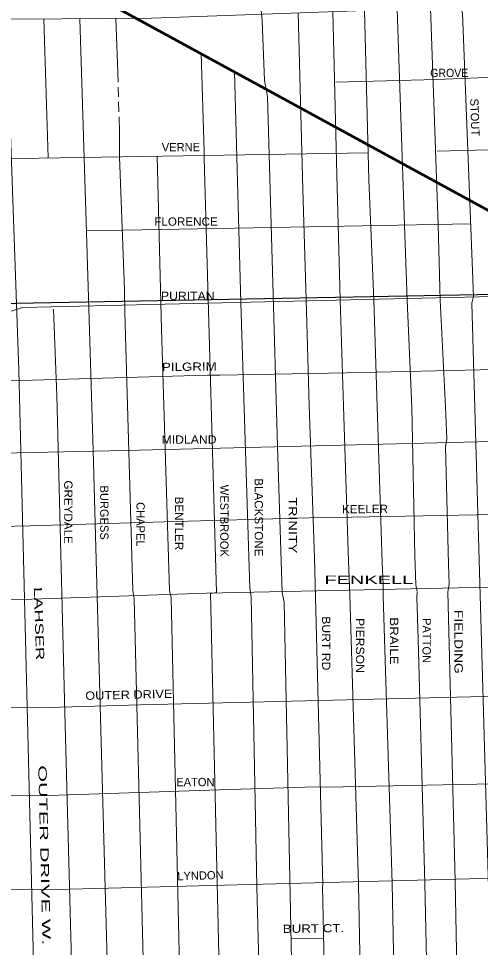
# Model space of a CAD drawing. Extents: x 34705 to 138605, y 34275 to 143551.
# Drawn here: x 43181 to 47356, y 121964 to 130370 of the extents above; entities that cross this region are included whole.
import ezdxf
from ezdxf.enums import TextEntityAlignment as Align

# ---------------------------------------------------------------- set-up
doc = ezdxf.new("R2010")
doc.units = 0
doc.header["$LTSCALE"] = 30
doc.linetypes.add('MEDIUM_DASHED', pattern=[4.5, 3, -1.5])
doc.layers.add('1', color=7, linetype='Continuous', lineweight=13)
doc.layers.add('11', color=7, linetype='Continuous', lineweight=13)

msp = doc.modelspace()

# ---------------------------------------------------------------- linework, layer by layer
at = {"layer": '1'}
for p, q in [((43409.69, 130365.58), (43448.1, 129108.82)), ((44058.94, 130369.94), (44077.55, 129885.39)), ((44092.23, 129381.05), (44093.84, 129119.21)), ((46965.59, 129170.84), (49690.15, 129237.44)), ((42382.42, 129091.68), (46341.01, 129155.36)), ((45644.76, 122041.69), (45938.46, 122045.94))]:
    msp.add_line(p, q, dxfattribs=at)
at = {"layer": '1', "linetype": 'MEDIUM_DASHED'}
msp.add_line((44077.55, 129885.39), (44090.41, 129443.69), dxfattribs=at)
at = {"layer": '1'}
for points in [[(45022.9, 140919.65), (45146.05, 135811.43), (45168.09, 135651.55), (45234.23, 133875), (45372.01, 130476.24), (45383.03, 130349.45), (45405.07, 129809.17), (45432.63, 129665.83), (45520.81, 126500.01), (45564.9, 125176.89), (45581.43, 125088.68), (45688.51, 119936.3)], [(42731.15, 140854.29), (42770.72, 138315.69), (42820.32, 138221.97), (42809.3, 138139.28), (42831.34, 137610.03), (42902.99, 132838.56), (43073.83, 130269.5), (43184.06, 127189.13), (43401.06, 118420.74)], [(47021.15, 134479.41), (47155.75, 130537.71), (47192.39, 130418.59), (47293.15, 127855.37), (47279.41, 127795.82), (47452.87, 121666.08), (47468.78, 120842.41)], [(35186.55, 130231.58), (35458.2, 130231.58), (37489.31, 130321.29), (37869.15, 130321.29), (40074.35, 130374.07), (43172.44, 130363.51), (44385.83, 130374.07), (48329.33, 130516.55), (49305.31, 130558.77), (49933.11, 130564.05), (54929.09, 130685.43), (56976.03, 130759.31), (58131.38, 130785.7), (58991.3, 130812.08), (60184.9, 130901.8), (61393.02, 130975.68), (61503.8, 130980.96), (63404.33, 131007.34), (65002.84, 131017.9), (66400.87, 131039.01), (66997.01, 131039.01), (67635.36, 131075.95), (68722.14, 131123.45), (70126.76, 131153.79)], [(46904.05, 130465.06), (46972.56, 128502.48), (46993.17, 127822.16), (47038.97, 126856.65), (47052.71, 126562.88), (47038.97, 126496.45), (47068.74, 125431.31), (47073.32, 125252.07), (47061.87, 125181.06), (47128.27, 122564.58), (47155.18, 121148.39), (47198.27, 119616.41)], [(45708.73, 130421.87), (45752.05, 128822.02), (45779.53, 127829.03), (45809.3, 126868.11), (45855.09, 125488.57), (45930.02, 122529.28), (45928.37, 122521.05), (45974.11, 120368.19), (46007.17, 119356.56), (46029.22, 118187.81), (46034.73, 117531.78), (46040.24, 117410.49), (46095.35, 114780.79), (46144.95, 112940.83), (46171.13, 112122.16), (46154.6, 112033.95), (46242.78, 109496.61), (46215.22, 109441.48), (46231.75, 108873.64), (46297.89, 106844.86)], [(46020.86, 130433.14), (46058.89, 128954.88), (46088.66, 127829.03), (46118.43, 126863.52), (46161.94, 125458.79), (46175.68, 125153.57), (46253.53, 122532.51), (46280.44, 121130.07), (46312.5, 119977.3), (46313.03, 119960.43)], [(46307.15, 130443.49), (46347.42, 128911.35), (46390.93, 127829.03), (46422.99, 126856.65), (46466.49, 125447.34), (46477.94, 125249.78), (46477.94, 125142.12), (46558.09, 122546.25), (46584.99, 121146.1), (46621.63, 119963.56)], [(46604.52, 130454.23), (46670.3, 128500.19), (46693.2, 127822.16), (46734.41, 126854.36), (46761.89, 125506.9), (46771.05, 125245.19), (46782.86, 125184.14)], [(43734.93, 130368.41), (43801.31, 128237.97), (43856.42, 126461.42), (44017.63, 120528.07)], [(44830.36, 130054.77), (44859.46, 129166.92), (44859.46, 129106.27), (44969.69, 125176.89), (44914.58, 125165.86), (45038, 119934.15)], [(45134.28, 129886.73), (45190.14, 127796.93), (45272.8, 125215.48), (45283.83, 125138.3), (45334.81, 122512.75), (45400.94, 119975.4), (45401.59, 119921.64)], [(46047.64, 129793.56), (46960.31, 129819.95), (48157.87, 129867.44), (51080.94, 129939.42)], [(44093.84, 129119.21), (44137.5, 127918.22), (44143.01, 127708.72), (44214.65, 125193.43), (44225.68, 125121.76), (44342.79, 120406.78)], [(44435.26, 129124.7), (44473.68, 127559.87), (44545.33, 125193.43), (44561.86, 125127.27), (44677.45, 119913.78)], [(43794.77, 128447.92), (45801, 128484.79), (46122.81, 128490.07), (47267.35, 128511.57)], [(41439.59, 127717.9), (41636.79, 127718.72), (41865.41, 127714.3), (42250.53, 127714.3), (43127.6, 127724.86), (43217.28, 127756.52), (48761.16, 127885.97)], [(43498.2, 127740.43), (43520.24, 127111.95), (43525.75, 126957.59), (43586.38, 124570.46), (43597.4, 124201.09), (43664.91, 121614.13)], [(39016.09, 127054.55), (40477.93, 127075.75), (40562.34, 127081.02), (42883.6, 127086.3), (44889.65, 127144.35), (45000.43, 127144.35), (46145.24, 127165.46), (49096.07, 127229.34)], [(39035.59, 126401.44), (40724.71, 126427.53), (41115.04, 126427.53), (41916.92, 126427.53), (42580.01, 126431.39), (43166, 126439.1), (44149.07, 126462.24), (50761.79, 126624.85)], [(39073.76, 125736.85), (40516.53, 125764.23), (40612.91, 125764.23), (40829.76, 125768.08), (41180.58, 125764.23), (41862.94, 125764.23), (42583.86, 125764.23), (43285.51, 125779.65), (44496.99, 125814.36), (45807.75, 125852.92), (46189.42, 125856.78), (48457.74, 125899.57)], [(39941.51, 125093.75), (40528.09, 125108.63), (40663.03, 125097.06), (40744.94, 125108.63), (41581.52, 125112.49), (42287.01, 125112.49), (43300.93, 125116.35), (44878.65, 125170.34), (48156.52, 125239.75), (49710.15, 125274.46), (51827.61, 125340.02), (53217.9, 125389.91), (53477.78, 125395.11), (53786.04, 125409.43)], [(46783.57, 125180.46), (46784.79, 125174.18), (46782.5, 125132.95), (46792.78, 124757.78)], [(46792.85, 124755.49), (46853.49, 122543.96), (46884.97, 121157.55), (46920.39, 119788.4)], [(40914.75, 124129.1), (43212.26, 124136.81), (43354.9, 124132.95), (44281.1, 124159.95), (49507.13, 124287.78), (49653.37, 124366.55), (49872.73, 124366.55), (53583.68, 124493.23)], [(40933.12, 123337.57), (41905.35, 123337.57), (41978.6, 123333.72), (43223.82, 123341.43), (43362.61, 123337.57), (44543.25, 123376.14), (44998.16, 123391.56), (45869.44, 123418.56), (45965.82, 123414.7), (48528.39, 123465.41)], [(41099.62, 122454.45), (41458.15, 122462.16), (41766.57, 122469.88), (42005.59, 122473.73), (43281.65, 122493.01), (43412.73, 122485.3), (47717.02, 122597.14), (53834.22, 122766.82), (57551.33, 122855.98)]]:
    msp.add_lwpolyline(points, dxfattribs=at)
at = {"layer": '1', "lineweight": 53}
msp.add_lwpolyline([(35051.57, 135383.85), (35124.2, 135323.83), (40544.24, 132389.75), (44352.38, 130313.49), (48721.15, 127927.26), (52359.24, 125955.06), (53781.74, 125169.15), (55156.63, 124418.97), (56043.46, 123936.71), (56442.24, 123716.41), (57585, 123085.31), (70109.98, 116247.42), (80624.23, 110526.89), (82336.58, 109591.28)], dxfattribs=at)
at = {"layer": '1', "lineweight": 25}
msp.add_lwpolyline([(37911.41, 127686.12), (38203.24, 127680.58), (38303.04, 127721.95), (38325.81, 127931.49), (38521.05, 128243.98), (39412.67, 127885.92), (39479.2, 127912.86), (39529.81, 127990.08), (39707.77, 127962.88), (39975.21, 127996.38), (40834.68, 127905.45), (41055.96, 127944.51), (41290.17, 127858.28), (41387.87, 127762.23), (48773.97, 127901.51)], dxfattribs=at)
at = {"layer": '11'}
msp.add_line((44090.43, 129442.8), (44092.23, 129381.05), dxfattribs=at)

# ---------------------------------------------------------------- texts
for s, width, p in [('GROVE', 0.95, (47074.16, 129840.65)), ('FLORENCE', 1.05, (44694.48, 128495.34)), ('PURITAN', 1.1, (44710.25, 127823.05))]:
    msp.add_text(s, height=75, dxfattribs=dict(at, width=width)).set_placement(p, align=Align.CENTER)
for s, rotation, p in [('STOUT', 271.867, (47268.46, 129474.92)), ('VERNE', 0.418, (44648.87, 129169.01)), ('BURGESS', 270, (43919, 125898.9)), ('WESTBROOK', 270, (45003.89, 125824.98)), ('CHAPEL', 270, (44246.56, 125793.27)), ('PATTON', 270, (46832.39, 124741.14)), ('LYNDON', 1.58, (44825.94, 122577.5))]:
    msp.add_text(s, height=75, rotation=rotation, dxfattribs=at).set_placement(p, align=Align.CENTER)
for s, rotation, width, p in [('PILGRIM', 0.655, 1.2, (44725.33, 127182.3)), ('MIDLAND', 0.236, 1.1, (44722.37, 126522.87)), ('GREYDALE', 270, 1.05, (43593.27, 125903.88)), ('BLACKSTONE', 270, 1.05, (45314.96, 125856.31)), ('BENTLER', 270, 1.05, (44594.91, 125801.78)), ('TRINITY', 270, 1.3, (45622.44, 125784.97)), ('KEELER', 0.407, 1.05, (46312.77, 125894.2)), ('FENKELL', 359.96, 1.8, (46347.15, 125254.22)), ('LAHSER', 271.84, 1.65, (43329.16, 124893.43)), ('FIELDING', 270, 1.25, (47121.48, 124729.93)), ('BURT RD', 270, 1.1, (45924.68, 124716.27)), ('PIERSON', 270, 1.1, (46230.71, 124696.71)), ('BRAILE', 270, 1.2, (46538.52, 124737.67)), ('OUTER DRIVE', 1.401, 1.15, (44178.52, 124213.8)), ('OUTER DRIVE W.', 271.374, 1.95, (43378.37, 122797.5)), ('BURT CT.', 0.821, 1.2, (45847.4, 122098.94))]:
    msp.add_text(s, height=75, rotation=rotation, dxfattribs=dict(at, width=width)).set_placement(p, align=Align.CENTER)
msp.add_text('EATON', height=75, dxfattribs=at).set_placement((44779.44, 123423.57), align=Align.CENTER)

doc.saveas('drawing.dxf')
